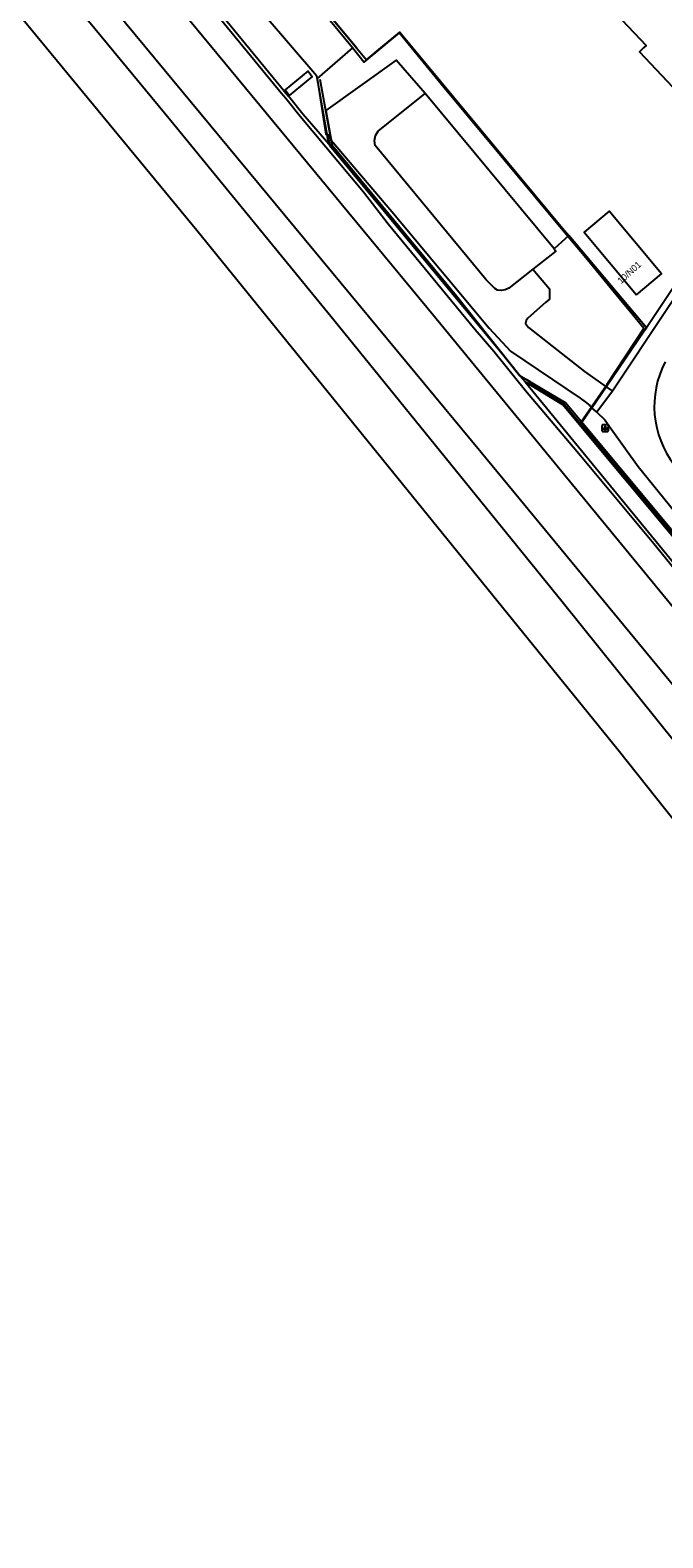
# Model space of a CAD drawing. Extents: x 158132 to 159658, y 385257 to 387209.
# Drawn here: x 158877.8 to 158975.2, y 385520.6 to 385752.7 of the extents above; entities that cross this region are included whole.
import ezdxf

# ---------------------------------------------------------------- set-up
doc = ezdxf.new("R2010")
doc.units = 0
for name, color, linetype in [('IMGEO_Berm_groen', 7, 'Continuous'), ('IMGEO_Grasland_overig', 7, 'Continuous'), ('IMGEO_Groenvoorziening', 7, 'Continuous'), ('IMGEO_Hek', 7, 'Continuous'), ('IMGEO_Lichtpunt', 7, 'Continuous'), ('IMGEO_Muur', 7, 'Continuous'), ('IMGEO_Pand', 7, 'Continuous'), ('IMGEO_Pand_nummerreeks', 7, 'Continuous'), ('IMGEO_Rijbaan_lokaal_gesloten', 7, 'Continuous'), ('IMGEO_Rijbaan_lokaal_open', 7, 'Continuous'), ('IMGEO_Spoor', 7, 'Continuous'), ('IMGEO_Spoorbaan_halfverhard', 7, 'Continuous'), ('IMGEO_Terreindeel_open', 7, 'Continuous'), ('IMGEO_Voetpad_op_trap', 7, 'Continuous')]:
    doc.layers.add(name, color=color, linetype=linetype)

msp = doc.modelspace()

# ---------------------------------------------------------------- linework, layer by layer
at = {"layer": 'IMGEO_Berm_groen'}
for points in [[(159004.39, 385754.5), (158972.66, 385706.93)], [(158966.47, 385697.83), (158972.33, 385706.44), (158972.66, 385706.93)]]:
    msp.add_lwpolyline(points, dxfattribs=at)
at = {"layer": 'IMGEO_Grasland_overig'}
for points in [[(158923.8, 385735.18), (158921.97, 385745.39), (158921.92, 385745.65), (158909.76, 385759.85), (158895.43, 385777.05), (158890.98, 385782.66), (158877.43, 385798.99), (158875.55, 385801.55), (158866.32, 385813.04), (158813.32, 385876.97), (158801.21, 385890.94), (158780.2, 385914.54), (158770.14, 385925.6), (158763.43, 385933.46), (158732.11, 385971.05), (158721.63, 385984.07), (158550.11, 386189.35), (158512.64, 386234.52), (158476.96, 386277.52), (158454.05, 386304.79), (158452.63, 386305.97)], [(158893.29, 385791.82), (158928.04, 385750), (158929.58, 385748.15), (158931.8, 385750), (158934.69, 385752.42), (158936.69, 385750), (158959.74, 385722.26), (158960.7, 385721.13)], [(158916.87, 385743.41), (158885.26, 385781.94), (158882.5, 385785.27)], [(158938.59, 385742.97), (158934.14, 385748.13), (158923.3, 385740.36), (158924.14, 385735.79)], [(158917.04, 385743.55), (158916.87, 385743.41)], [(158916.87, 385743.41), (158917.56, 385742.56)], [(158917.56, 385742.56), (158917.73, 385742.69)], [(158923.8, 385735.18), (158919.78, 385739.8), (158917.56, 385742.56)], [(158924.3, 385734.97), (158923.8, 385735.18)], [(158924.14, 385735.79), (158933.46, 385724.83), (158948.44, 385706.84), (158951.75, 385703.32), (158962.45, 385696.07), (158963.22, 385695.51), (158963.98, 385694.97), (158964.26, 385694.58)], [(158924.14, 385735.79), (158924.3, 385734.97)], [(158924.3, 385734.97), (158943.45, 385711.79), (158953.18, 385699.51)], [(158960.7, 385721.13), (158958.45, 385719.07)], [(158962.61, 385692.47), (158960.22, 385695.34), (158953.18, 385699.51)], [(158953.18, 385699.51), (158953.98, 385698.58)], [(158962.32, 385692.02), (158959.8, 385695.06), (158953.98, 385698.58)], [(158953.98, 385698.58), (158991.95, 385652.3), (159022.26, 385614.92), (159049.63, 385580.5), (159065.98, 385559.03), (159065.99, 385559.03)], [(158964.26, 385694.58), (158962.73, 385692.34)], [(158962.32, 385692.02), (158962.61, 385692.47)], [(159023.17, 385618.87), (159015.84, 385627.86), (158962.32, 385692.02)], [(158962.73, 385692.34), (158962.61, 385692.47)]]:
    msp.add_lwpolyline(points, dxfattribs=at)
at = {"layer": 'IMGEO_Groenvoorziening'}
msp.add_lwpolyline([(158962.73, 385692.34), (158962.69, 385692.28), (158988.63, 385661.23), (158990.68, 385658.81)], dxfattribs=at)
at = {"layer": 'IMGEO_Hek'}
for points in [[(158928.04, 385750), (158893.29, 385791.82)], [(158962.46, 385692.22), (158966.65, 385698.25), (158972.27, 385706.81), (158970.71, 385708.7), (158967.57, 385712.53), (158963.6, 385717.37), (158960.36, 385721.23), (158941.08, 385744.42), (158934.61, 385752.33), (158929.15, 385747.79), (158927.4, 385749.99), (158922.76, 385755.66), (158916.28, 385763.67), (158904.84, 385777.67), (158898.32, 385785.62), (158893.43, 385791.54)], [(158931.8, 385750), (158934.69, 385752.42), (158936.69, 385750)], [(158927.4, 385749.99), (158922, 385745.28), (158923.32, 385736.7), (158923.64, 385736.74)], [(158928.04, 385750), (158929.58, 385748.15)], [(158931.8, 385750), (158929.58, 385748.15)], [(158936.69, 385750), (158959.74, 385722.26)], [(158923.64, 385736.74), (158923.89, 385735.02), (158934.11, 385722.7), (158950.08, 385703.36), (158953.23, 385699.54), (158954.73, 385698.69), (158954.61, 385698.43), (158959.85, 385695.35), (158967.8, 385685.8), (158975.82, 385676.2), (158983.82, 385666.58), (158993.47, 385655.01), (159001.45, 385645.37), (159015.71, 385628.27), (159022.08, 385620.55), (159030.13, 385610.93), (159041.19, 385597.53), (159065.26, 385568.73), (159079.54, 385551.51), (159087.54, 385541.87), (159092.37, 385536.15), (159099.04, 385528.11)], [(158959.74, 385722.26), (158972.66, 385706.93), (158972.33, 385706.44)], [(158972.33, 385706.44), (158966.47, 385697.83)], [(158966.47, 385697.83), (158964.26, 385694.58)], [(158964.26, 385694.58), (158962.69, 385692.28)], [(158962.69, 385692.28), (158988.63, 385661.23), (159000, 385647.81), (159099.09, 385528.71)]]:
    msp.add_lwpolyline(points, dxfattribs=at)
at = {"layer": 'IMGEO_Lichtpunt'}
for p, q in [((158965.82, 385691.87), (158965.82, 385691.07)), ((158965.82, 385691.87), (158965.82, 385691.07)), ((158966.73, 385691.97), (158965.92, 385691.97)), ((158966.73, 385691.97), (158965.92, 385691.97)), ((158965.92, 385690.97), (158966.73, 385690.97)), ((158965.92, 385690.97), (158966.73, 385690.97)), ((158966.82, 385691.07), (158966.82, 385691.87)), ((158966.82, 385691.07), (158966.82, 385691.87))]:
    msp.add_line(p, q, dxfattribs=at)
for points in [[(158966.2, 385691.54), (158966.24, 385691.51), (158966.05, 385691.25), (158966.01, 385691.27), (158966.2, 385691.54)], [(158966.3, 385691.49), (158966.35, 385691.49), (158966.35, 385691.17), (158966.3, 385691.17), (158966.3, 385691.49)], [(158966.41, 385691.51), (158966.45, 385691.54), (158966.63, 385691.27), (158966.6, 385691.25), (158966.41, 385691.51)]]:
    msp.add_lwpolyline(points, dxfattribs=at)
msp.add_circle((158966.32, 385691.67), 0.0994, dxfattribs=at)
for centre, start, end in [((158965.92, 385691.87), 90, 180), ((158965.92, 385691.87), 90, 180), ((158965.92, 385691.07), 180, 270), ((158965.92, 385691.07), 180, 270), ((158966.73, 385691.87), 0, 90), ((158966.73, 385691.87), 0, 90), ((158966.73, 385691.07), 270, 0), ((158966.73, 385691.07), 270, 360)]:
    msp.add_arc(centre, 0.0946, start, end, dxfattribs=at)
at = {"layer": 'IMGEO_Muur'}
for points in [[(158962.61, 385692.47), (158960.22, 385695.34), (158953.18, 385699.51), (158943.45, 385711.79), (158924.3, 385734.97), (158922.42, 385745.12)], [(159098.74, 385528.41), (159099, 385528.64), (159045.88, 385592.6), (158962.61, 385692.47)]]:
    msp.add_lwpolyline(points, dxfattribs=at)
at = {"layer": 'IMGEO_Pand'}
for points in [[(158997.19, 385756.65), (158983.32, 385771.28), (158976.92, 385765.21), (158949.77, 385793.86), (158945.14, 385789.48), (158939.12, 385795.84), (158937.7, 385794.49), (158934.07, 385791.05), (158972.61, 385750.37), (158972.21, 385750), (158971.58, 385749.4), (158980.07, 385740.44), (158990.17, 385750), (158991.67, 385751.42), (158997.19, 385756.65)], [(158955.2, 385715.93), (158951.5, 385712.99), (158950.93, 385712.74), (158950.34, 385712.65), (158949.75, 385712.7), (158949.32, 385712.94), (158948, 385714.31), (158930.92, 385734.96), (158930.83, 385735.75), (158930.95, 385736.51), (158931.38, 385737.2), (158938.59, 385742.97)], [(158958.45, 385719.07), (158938.59, 385742.97)], [(158971.13, 385711.98), (158975, 385715.22), (158966.94, 385724.86), (158963.07, 385721.63), (158971.13, 385711.98)], [(158958.45, 385719.07), (158958.73, 385718.73), (158955.2, 385715.93)]]:
    msp.add_lwpolyline(points, dxfattribs=at)
at = {"layer": 'IMGEO_Rijbaan_lokaal_gesloten'}
for points in [[(159004.75, 385753.06), (159002.63, 385749.99), (158992.66, 385735.04), (158967.43, 385697.18)], [(158967.43, 385697.18), (158965.06, 385693.92)], [(158965.06, 385693.92), (158966.27, 385692.72), (158967.24, 385691.35), (158971.39, 385685.58), (159027.52, 385616.28), (159051.79, 385587.72), (159126.09, 385500), (159144.91, 385476.95), (159192.81, 385420.08), (159265.13, 385334.67)]]:
    msp.add_lwpolyline(points, dxfattribs=at)
msp.add_arc((158988.64, 385694.83), 14.76, 152.3355, 217.6377, dxfattribs=at)
at = {"layer": 'IMGEO_Rijbaan_lokaal_open'}
for points in [[(158964.26, 385694.58), (158966.47, 385697.83)], [(158966.47, 385697.83), (158967.43, 385697.18)], [(158965.06, 385693.92), (158964.26, 385694.58)]]:
    msp.add_lwpolyline(points, dxfattribs=at)
at = {"layer": 'IMGEO_Spoor'}
for points in [[(158183.23, 386593.64), (158250.34, 386512.27), (158320.88, 386427.2), (158390.63, 386342.73), (158437.14, 386286.56), (158475.32, 386240.27), (158493.61, 386217.92), (158666.6, 386008.62), (158712.98, 385952.66), (158746.85, 385911.48), (158804.33, 385842.16), (158903.44, 385721.96), (158968.31, 385641.91), (158993.3, 385610.47), (159052.26, 385536.6), (159079.06, 385503.44), (159104.74, 385472.03), (159179.39, 385381.3), (159222.18, 385329.69), (159276.78, 385263.61)], [(158305.02, 386458.21), (158323.8, 386435.6), (158392.22, 386352.85), (158899.46, 385738.82), (158924.54, 385708.13), (158959.68, 385664.77), (158977.24, 385642.93), (159021.11, 385587.17), (159057.71, 385540.32), (159087.55, 385502.29), (159118.56, 385463.18), (159158.87, 385413.29), (159192.22, 385372.58), (159280.07, 385266.34)], [(158391.09, 386360.72), (158491.13, 386239.56), (158538.07, 386183.03), (158587.16, 386123.49), (158724.17, 385957.81), (158781.97, 385887.68), (158833.11, 385825.86), (158873.91, 385776.35), (158947.25, 385687.78), (158974.98, 385654.09), (158999.8, 385623.89), (159031.62, 385584.85), (159070.24, 385536.67), (159150.39, 385436.4), (159181.35, 385398.01), (159212.16, 385360.43), (159269.58, 385291.16), (159286.01, 385271.25)], [(158467.76, 386280.04), (158481.71, 386263.38), (158516.18, 386221.44), (158744.02, 385945.82), (158789.16, 385891.01), (158837.92, 385832.2), (158939.86, 385708.89), (158979.91, 385660.12), (159034.3, 385592.75), (159082.74, 385531.41), (159124.36, 385478.04), (159172.25, 385417.35), (159208.96, 385371.65), (159261.54, 385307.65), (159289.31, 385273.98)]]:
    msp.add_lwpolyline(points, dxfattribs=at)
at = {"layer": 'IMGEO_Spoorbaan_halfverhard'}
msp.add_lwpolyline([(159098.43, 385517.51), (159093.07, 385524.17), (159087.27, 385531.94), (159074.72, 385547.35), (159065.71, 385558.76), (159045.24, 385585.01), (159022.75, 385613.33), (159001.23, 385639.96), (158985.66, 385659.25), (158976.96, 385669.81), (158973.79, 385673.65), (158967.41, 385681.35), (158962.53, 385687.2), (158954.07, 385697.22), (158949.18, 385703.24), (158946.33, 385706.62), (158932.93, 385722.87), (158929.12, 385727.78), (158919.35, 385739.45), (158917.14, 385742.21), (158916.44, 385743.06), (158884.84, 385781.59)], dxfattribs=at)
at = {"layer": 'IMGEO_Terreindeel_open'}
for points in [[(158972.66, 385706.93), (158960.7, 385721.13)], [(158955.2, 385715.93), (158957.73, 385712.89), (158957.74, 385711.34), (158957.11, 385710.78), (158954.41, 385708.37), (158954.14, 385708.02), (158954.08, 385707.58), (158954.54, 385706.95), (158963.13, 385700.18), (158966.47, 385697.83)]]:
    msp.add_lwpolyline(points, dxfattribs=at)
at = {"layer": 'IMGEO_Voetpad_op_trap'}
for points in [[(158917.73, 385742.69), (158921.23, 385745.55), (158920.53, 385746.4), (158917.04, 385743.55)], [(158917.04, 385743.55), (158917.73, 385742.69)]]:
    msp.add_lwpolyline(points, dxfattribs=at)

# ---------------------------------------------------------------- texts
at = {"layer": 'IMGEO_Pand_nummerreeks'}
msp.add_text('10/N01', height=1, rotation=42.3989, dxfattribs=at).set_placement((158968.78, 385713.6))

doc.saveas('drawing.dxf')
